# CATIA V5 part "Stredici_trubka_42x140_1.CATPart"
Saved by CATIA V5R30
Part number: Stredici_trubka_42x140_1
Definition: E 1160_42x140_2
Nomenclature: E 1160_42x140_2
Source: Unknown
Description: PART--DESC
Bounding box of the stored display mesh (mm): x -208 to -166, y 116.01 to 157.99, z -258 to -118
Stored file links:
  E:\Bakalarka\Model\Forma_v7\Stredici_trubka_42x140_1.CATPart
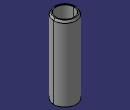
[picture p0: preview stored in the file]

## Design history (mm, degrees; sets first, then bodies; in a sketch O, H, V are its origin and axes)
Body1 "MANIFOLD_SOLID_BREP #3890" (main body)
  Solid1: solid without history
